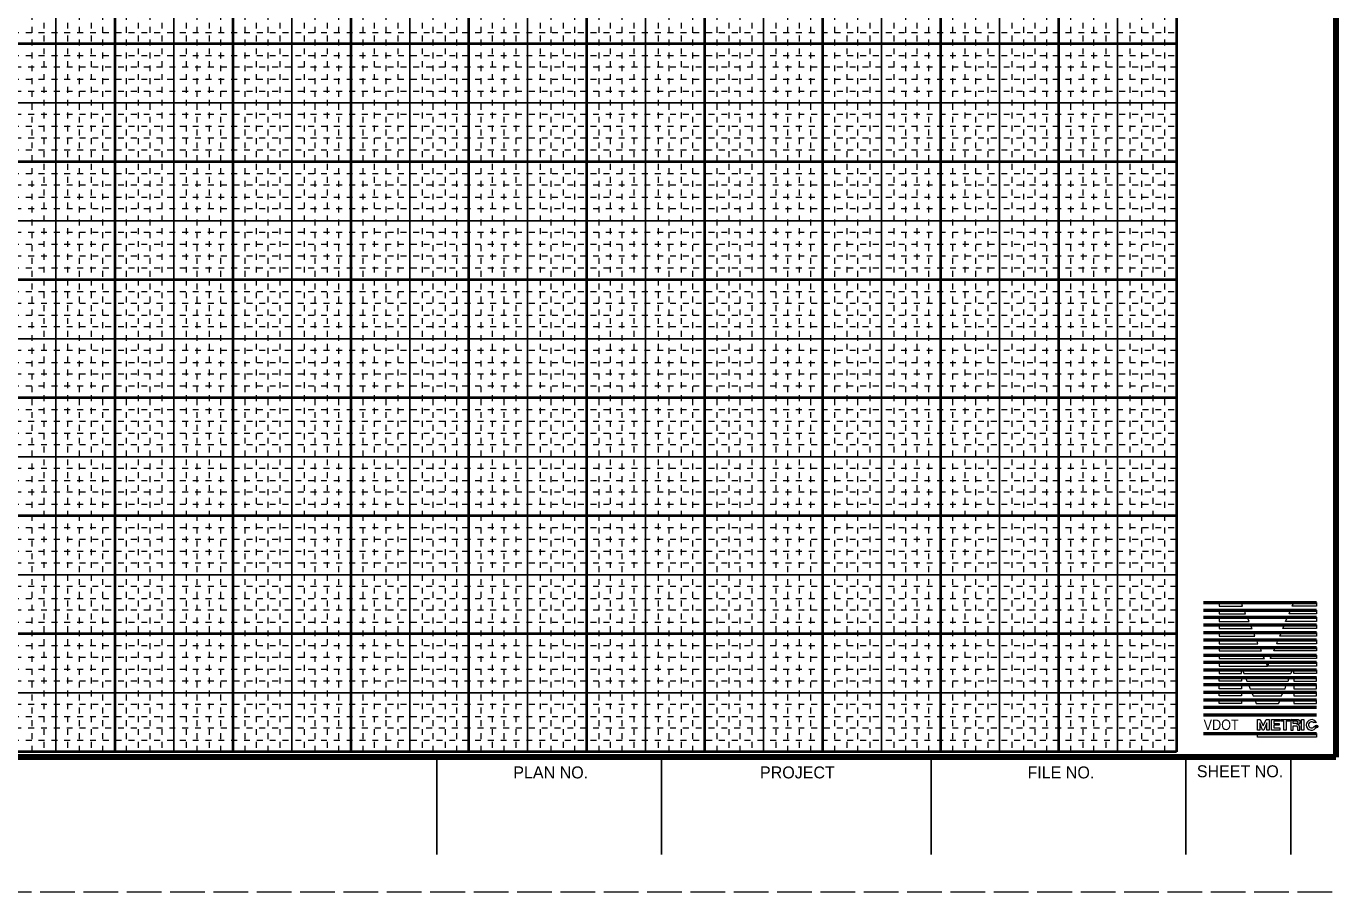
# Model space of a CAD drawing. Extents: x 224742 to 224831, y 224746 to 227695.
# Drawn here: x 224808.86 to 224831.11, y 225807.99 to 225822.66 of the extents above; entities that cross this region are included whole.
import ezdxf
from ezdxf.enums import TextEntityAlignment as Align

# ---------------------------------------------------------------- set-up
doc = ezdxf.new("R2010")
doc.units = 0
doc.header["$LTSCALE"] = 0.098
doc.header["$PDMODE"] = 32
doc.header["$PDSIZE"] = 0.049
doc.linetypes.add('DOTTED', pattern=[1.5, 0.3, -1.2])
doc.linetypes.add('LONG_DASHED', pattern=[7.5, 6, -1.5])
for name, color, linetype, lineweight in [('59', 7, 'DOTTED', 13), ('60', 7, 'Continuous', 40), ('61', 7, 'Continuous', 13), ('63', 7, 'LONG_DASHED', 13)]:
    doc.layers.add(name, color=color, linetype=linetype, lineweight=lineweight)

msp = doc.modelspace()

# ---------------------------------------------------------------- linework, layer by layer
at = {"layer": '59'}
for p, q in [((224808.9648, 225810.3649), (224808.9648, 225860.3649)), ((224809.1648, 225860.3649), (224809.1648, 225810.3649)), ((224809.5648, 225860.3649), (224809.5648, 225810.3649)), ((224809.7648, 225810.3649), (224809.7648, 225860.3649)), ((224809.9648, 225860.3649), (224809.9648, 225810.3649)), ((224810.1648, 225810.3649), (224810.1648, 225860.3649)), ((224810.5648, 225810.3649), (224810.5648, 225860.3649)), ((224810.7648, 225860.3649), (224810.7648, 225810.3649)), ((224810.9648, 225810.3649), (224810.9648, 225860.3649)), ((224811.1648, 225860.3649), (224811.1648, 225810.3649)), ((224811.5748, 225860.3649), (224811.5748, 225810.3649)), ((224811.7648, 225810.3649), (224811.7648, 225860.3649)), ((224811.9648, 225860.3649), (224811.9648, 225810.3649)), ((224812.1648, 225810.3649), (224812.1648, 225860.3649)), ((224812.5748, 225810.3649), (224812.5748, 225860.3649)), ((224812.7648, 225860.3649), (224812.7648, 225810.3649)), ((224812.9648, 225810.3649), (224812.9648, 225860.3649)), ((224813.1648, 225860.3649), (224813.1648, 225810.3649)), ((224813.5748, 225860.3649), (224813.5748, 225810.3649)), ((224813.7648, 225810.3649), (224813.7648, 225860.3649)), ((224813.9648, 225860.3649), (224813.9648, 225810.3649)), ((224814.1648, 225810.3649), (224814.1648, 225860.3649)), ((224814.5748, 225810.3649), (224814.5748, 225860.3649)), ((224814.7648, 225860.3649), (224814.7648, 225810.3649)), ((224814.9648, 225810.3649), (224814.9648, 225860.3649)), ((224815.1648, 225860.3649), (224815.1648, 225810.3649)), ((224815.5748, 225860.3649), (224815.5748, 225810.3649)), ((224815.7648, 225810.3649), (224815.7648, 225860.3649)), ((224815.9648, 225860.3649), (224815.9648, 225810.3649)), ((224816.1648, 225810.3649), (224816.1648, 225860.3649)), ((224816.5748, 225810.3649), (224816.5748, 225860.3649)), ((224816.7648, 225860.3649), (224816.7648, 225810.3649)), ((224816.9648, 225810.3649), (224816.9648, 225860.3649)), ((224817.1648, 225860.3649), (224817.1648, 225810.3649)), ((224817.5748, 225860.3649), (224817.5748, 225810.3649)), ((224817.7648, 225810.3649), (224817.7648, 225860.3649)), ((224817.9648, 225860.3649), (224817.9648, 225810.3649)), ((224818.1648, 225810.3649), (224818.1648, 225860.3649)), ((224818.5748, 225810.3649), (224818.5748, 225860.3649)), ((224818.7648, 225860.3649), (224818.7648, 225810.3649)), ((224818.9648, 225810.3649), (224818.9648, 225860.3649)), ((224819.1648, 225860.3649), (224819.1648, 225810.3649)), ((224819.5748, 225860.3649), (224819.5748, 225810.3649)), ((224819.7648, 225810.3649), (224819.7648, 225860.3649)), ((224819.9648, 225860.3649), (224819.9648, 225810.3649)), ((224820.1648, 225810.3649), (224820.1648, 225860.3649)), ((224820.5748, 225810.3649), (224820.5748, 225860.3649)), ((224820.7748, 225860.3649), (224820.7748, 225810.3649)), ((224820.9648, 225810.3649), (224820.9648, 225860.3649)), ((224821.1648, 225860.3649), (224821.1648, 225810.3649)), ((224821.5748, 225860.3649), (224821.5748, 225810.3649)), ((224821.7748, 225810.3649), (224821.7748, 225860.3649)), ((224821.9648, 225860.3649), (224821.9648, 225810.3649)), ((224822.1648, 225810.3649), (224822.1648, 225860.3649)), ((224822.5748, 225810.3649), (224822.5748, 225860.3649)), ((224822.7748, 225860.3649), (224822.7748, 225810.3649)), ((224822.9648, 225810.3649), (224822.9648, 225860.3649)), ((224823.1648, 225860.3649), (224823.1648, 225810.3649)), ((224823.5748, 225860.3649), (224823.5748, 225810.3649)), ((224823.7748, 225810.3649), (224823.7748, 225860.3649)), ((224823.9648, 225860.3649), (224823.9648, 225810.3649)), ((224824.1648, 225810.3649), (224824.1648, 225860.3649)), ((224824.5748, 225810.3649), (224824.5748, 225860.3649)), ((224824.7748, 225860.3649), (224824.7748, 225810.3649)), ((224824.9648, 225810.3649), (224824.9648, 225860.3649)), ((224825.1648, 225860.3649), (224825.1648, 225810.3649)), ((224825.5748, 225860.3649), (224825.5748, 225810.3649)), ((224825.7748, 225810.3649), (224825.7748, 225860.3649)), ((224825.9648, 225860.3649), (224825.9648, 225810.3649)), ((224826.1648, 225810.3649), (224826.1648, 225860.3649)), ((224826.5748, 225810.3649), (224826.5748, 225860.3649)), ((224826.7748, 225860.3649), (224826.7748, 225810.3649)), ((224826.9648, 225810.3649), (224826.9648, 225860.3649)), ((224827.1648, 225860.3649), (224827.1648, 225810.3649)), ((224827.5748, 225860.3649), (224827.5748, 225810.3649)), ((224827.7748, 225810.3649), (224827.7748, 225860.3649)), ((224827.9648, 225860.3649), (224827.9648, 225810.3649)), ((224828.1648, 225810.3649), (224828.1648, 225860.3649)), ((224748.3648, 225822.5549), (224828.3648, 225822.5549)), ((224748.3648, 225822.1649), (224828.3648, 225822.1649)), ((224828.3648, 225821.9649), (224748.3648, 225821.9649)), ((224748.3648, 225821.7649), (224828.3648, 225821.7649)), ((224828.3648, 225821.5549), (224748.3648, 225821.5549)), ((224828.3648, 225821.1649), (224748.3648, 225821.1649)), ((224748.3648, 225820.9649), (224828.3648, 225820.9649)), ((224828.3648, 225820.7649), (224748.3648, 225820.7649)), ((224748.3648, 225820.5649), (224828.3648, 225820.5649)), ((224748.3648, 225820.1649), (224828.3648, 225820.1649)), ((224828.3648, 225819.9649), (224748.3648, 225819.9649)), ((224748.3648, 225819.7649), (224828.3648, 225819.7649)), ((224828.3648, 225819.5649), (224748.3648, 225819.5649)), ((224828.3648, 225819.1649), (224748.3648, 225819.1649)), ((224748.3648, 225818.9649), (224828.3648, 225818.9649)), ((224828.3648, 225818.7649), (224748.3648, 225818.7649)), ((224748.3648, 225818.5649), (224828.3648, 225818.5649)), ((224748.3648, 225818.1649), (224828.3648, 225818.1649)), ((224828.3648, 225817.9649), (224748.3648, 225817.9649)), ((224748.3648, 225817.7649), (224828.3648, 225817.7649)), ((224828.3648, 225817.5649), (224748.3648, 225817.5649)), ((224828.3648, 225817.1649), (224748.3648, 225817.1649)), ((224748.3648, 225816.9649), (224828.3648, 225816.9649)), ((224828.3648, 225816.7649), (224748.3648, 225816.7649)), ((224748.3648, 225816.5649), (224828.3648, 225816.5649)), ((224748.3648, 225816.1649), (224828.3648, 225816.1649)), ((224828.3648, 225815.9649), (224748.3648, 225815.9649)), ((224748.3648, 225815.7649), (224828.3648, 225815.7649)), ((224828.3648, 225815.5649), (224748.3648, 225815.5649)), ((224828.3648, 225815.1649), (224748.3648, 225815.1649)), ((224748.3648, 225814.9649), (224828.3648, 225814.9649)), ((224828.3648, 225814.7649), (224748.3648, 225814.7649)), ((224748.3648, 225814.5649), (224828.3648, 225814.5649)), ((224748.3648, 225814.1649), (224828.3648, 225814.1649)), ((224828.3648, 225813.9649), (224748.3648, 225813.9649)), ((224748.3648, 225813.7649), (224828.3648, 225813.7649)), ((224828.3648, 225813.5649), (224748.3648, 225813.5649)), ((224828.3648, 225813.1649), (224748.3648, 225813.1649)), ((224748.3648, 225812.9649), (224828.3648, 225812.9649)), ((224828.3648, 225812.7649), (224748.3648, 225812.7649)), ((224748.3648, 225812.5649), (224828.3648, 225812.5649)), ((224748.3648, 225812.1649), (224828.3648, 225812.1649)), ((224828.3648, 225811.9649), (224748.3648, 225811.9649)), ((224748.3648, 225811.7649), (224828.3648, 225811.7649)), ((224828.3648, 225811.5649), (224748.3648, 225811.5649)), ((224828.3648, 225811.1649), (224748.3648, 225811.1649)), ((224748.3648, 225810.9649), (224828.3648, 225810.9649)), ((224828.3648, 225810.7649), (224748.3648, 225810.7649)), ((224748.3648, 225810.5649), (224828.3648, 225810.5649))]:
    msp.add_line(p, q, dxfattribs=at)
at = {"layer": '59', "linetype": 'Continuous', "lineweight": 25}
for p, q in [((224809.3648, 225810.3649), (224809.3648, 225860.3649)), ((224811.3648, 225810.3649), (224811.3648, 225860.3649)), ((224813.3648, 225810.3649), (224813.3648, 225860.3649)), ((224815.3648, 225810.3649), (224815.3648, 225860.3649)), ((224817.3648, 225810.3649), (224817.3648, 225860.3649)), ((224819.3648, 225810.3649), (224819.3648, 225860.3649)), ((224821.3648, 225810.3649), (224821.3648, 225860.3649)), ((224823.3648, 225810.3649), (224823.3648, 225860.3649)), ((224825.3648, 225810.3649), (224825.3648, 225860.3649)), ((224827.3648, 225810.3649), (224827.3648, 225860.3649)), ((224748.3648, 225821.3649), (224828.3648, 225821.3649)), ((224748.3648, 225819.3649), (224828.3648, 225819.3649)), ((224748.3648, 225817.3649), (224828.3648, 225817.3649)), ((224748.3648, 225815.3649), (224828.3648, 225815.3649)), ((224748.3648, 225813.3649), (224828.3648, 225813.3649)), ((224748.3648, 225811.3649), (224828.3648, 225811.3649))]:
    msp.add_line(p, q, dxfattribs=at)
at = {"layer": '60'}
for p, q in [((224810.3648, 225860.3649), (224810.3648, 225810.3649)), ((224812.3648, 225860.3649), (224812.3648, 225810.3649)), ((224814.3648, 225860.3649), (224814.3648, 225810.3649)), ((224816.3648, 225860.3649), (224816.3648, 225810.3649)), ((224818.3648, 225860.3649), (224818.3648, 225810.3649)), ((224820.3648, 225860.3649), (224820.3648, 225810.3649)), ((224822.3648, 225860.3649), (224822.3648, 225810.3649)), ((224824.3648, 225860.3649), (224824.3648, 225810.3649)), ((224826.3648, 225860.3649), (224826.3648, 225810.3649)), ((224828.3648, 225860.3649), (224828.3648, 225810.3649)), ((224828.3648, 225822.3649), (224748.3648, 225822.3649)), ((224828.3648, 225820.3649), (224748.3648, 225820.3649)), ((224828.3648, 225818.3649), (224748.3648, 225818.3649)), ((224828.3648, 225816.3649), (224748.3648, 225816.3649)), ((224828.3648, 225814.3649), (224748.3648, 225814.3649)), ((224828.3648, 225812.3649), (224748.3648, 225812.3649)), ((224828.3648, 225810.3649), (224748.3648, 225810.3649))]:
    msp.add_line(p, q, dxfattribs=at)
at = {"layer": '61', "lineweight": 158}
for p, q in [((224831.0648, 225864.1249), (224831.0648, 225810.2749)), ((224831.0648, 225810.2749), (224745.7148, 225810.2749))]:
    msp.add_line(p, q, dxfattribs=at)
at = {"layer": '61', "lineweight": 53}
for p, q in [((224828.8248, 225812.8949), (224830.7348, 225812.8949)), ((224828.8248, 225812.7649), (224830.7348, 225812.7649)), ((224828.8248, 225812.6449), (224830.7348, 225812.6449)), ((224828.8248, 225812.5149), (224830.7348, 225812.5149)), ((224828.8248, 225812.3849), (224830.7348, 225812.3849)), ((224828.8248, 225812.2649), (224830.7348, 225812.2649)), ((224828.8248, 225812.1349), (224830.7348, 225812.1349)), ((224828.8248, 225812.0049), (224830.7348, 225812.0049)), ((224828.8248, 225811.8849), (224830.7348, 225811.8849)), ((224828.8248, 225811.7549), (224830.7348, 225811.7549)), ((224828.8248, 225811.6249), (224830.7348, 225811.6249)), ((224828.8248, 225811.5049), (224830.7348, 225811.5049)), ((224828.8248, 225811.3749), (224830.7348, 225811.3749)), ((224828.8248, 225811.2449), (224830.7348, 225811.2449)), ((224828.8248, 225811.1249), (224830.7348, 225811.1249)), ((224828.8248, 225810.9949), (224830.7348, 225810.9949)), ((224828.8248, 225810.6749), (224830.7348, 225810.6749))]:
    msp.add_line(p, q, dxfattribs=at)
at = {"layer": '61'}
for p, q in [((224829.0848, 225812.0749), (224829.8048, 225812.0749)), ((224829.0848, 225811.9449), (224829.8548, 225811.9449)), ((224830.7348, 225811.9449), (224829.9548, 225811.9449)), ((224830.7348, 225812.0749), (224830.0148, 225812.0749)), ((224829.8848, 225811.8849), (224829.9048, 225811.8149)), ((224829.9348, 225811.8849), (224829.9048, 225811.8149)), ((224830.7348, 225810.8649), (224830.6848, 225810.8649)), ((224830.6948, 225810.7949), (224830.7348, 225810.7949))]:
    msp.add_line(p, q, dxfattribs=at)
at = {"layer": '61', "lineweight": 25}
for p, q in [((224831.0648, 225810.2749), (224815.8248, 225810.2749)), ((224815.8248, 225810.2749), (224815.8248, 225808.6249)), ((224831.0648, 225810.2749), (224815.8248, 225810.2749)), ((224819.6348, 225810.2749), (224819.6348, 225808.6249)), ((224824.2048, 225808.6249), (224824.2048, 225810.2749)), ((224828.5248, 225808.6249), (224828.5248, 225810.2749)), ((224830.3048, 225808.6249), (224830.3048, 225810.2749))]:
    msp.add_line(p, q, dxfattribs=at)
at = {"layer": '61'}
for points in [[(224829.0848, 225812.8949), (224829.0848, 225812.8349), (224829.4848, 225812.8349), (224829.4648, 225812.8949)], [(224830.7348, 225812.8949), (224830.7348, 225812.8349), (224830.3248, 225812.8349), (224830.3548, 225812.8949)], [(224829.0848, 225812.7649), (224829.0848, 225812.7049), (224829.5348, 225812.7049), (224829.5148, 225812.7649)], [(224829.0848, 225812.6449), (224829.0848, 225812.5749), (224829.5948, 225812.5749), (224829.5648, 225812.6449)], [(224830.7348, 225812.6449), (224830.7348, 225812.5749), (224830.2148, 225812.5749), (224830.2448, 225812.6449)], [(224830.7348, 225812.7649), (224830.7348, 225812.7049), (224830.2748, 225812.7049), (224830.2948, 225812.7649)], [(224829.0848, 225812.5149), (224829.0848, 225812.4549), (224829.6448, 225812.4549), (224829.6148, 225812.5149)], [(224829.0848, 225812.3849), (224829.0848, 225812.3249), (224829.6948, 225812.3249), (224829.6748, 225812.3849)], [(224830.7348, 225812.3849), (224830.7348, 225812.3249), (224830.1148, 225812.3249), (224830.1448, 225812.3849)], [(224830.7348, 225812.5149), (224830.7348, 225812.4549), (224830.1648, 225812.4549), (224830.1948, 225812.5149)], [(224829.0848, 225812.2649), (224829.0848, 225812.1949), (224829.7448, 225812.1949), (224829.7248, 225812.2649)], [(224830.7348, 225812.2649), (224830.7348, 225812.1949), (224830.0648, 225812.1949), (224830.0848, 225812.2649)], [(224829.0848, 225812.1349), (224829.0848, 225812.0749), (224829.8048, 225812.0749), (224829.7748, 225812.1349)], [(224829.0848, 225812.0049), (224829.0848, 225811.9449), (224829.8548, 225811.9449), (224829.8248, 225812.0049)], [(224830.7348, 225812.0049), (224830.7348, 225811.9449), (224829.9548, 225811.9449), (224829.9848, 225812.0049)], [(224830.7348, 225812.1349), (224830.7348, 225812.0749), (224830.0148, 225812.0749), (224830.0348, 225812.1349)], [(224829.0848, 225811.8849), (224829.0848, 225811.8149), (224829.9048, 225811.8149), (224829.8848, 225811.8849)], [(224829.0848, 225811.7549), (224829.0848, 225811.6949), (224829.4648, 225811.6949), (224829.4648, 225811.7549)], [(224829.4848, 225811.7549), (224829.5048, 225811.6949), (224830.3048, 225811.6949), (224830.3348, 225811.7549)], [(224830.7348, 225811.8849), (224830.7348, 225811.8149), (224829.9048, 225811.8149), (224829.9348, 225811.8849)], [(224830.7348, 225811.7549), (224830.7348, 225811.6949), (224830.3548, 225811.6949), (224830.3548, 225811.7549)], [(224829.0848, 225811.6249), (224829.4648, 225811.6249), (224829.4648, 225811.5649), (224829.0848, 225811.5649)], [(224829.0848, 225811.5049), (224829.4648, 225811.5049), (224829.4648, 225811.4349), (224829.0848, 225811.4349)], [(224829.5348, 225811.6249), (224829.5548, 225811.5649), (224830.2548, 225811.5649), (224830.2748, 225811.6249)], [(224829.5848, 225811.5049), (224829.6148, 225811.4349), (224830.2048, 225811.4349), (224830.2248, 225811.5049)], [(224830.7348, 225811.6249), (224830.3548, 225811.6249), (224830.3548, 225811.5649), (224830.7348, 225811.5649)], [(224830.7348, 225811.5049), (224830.3548, 225811.5049), (224830.3548, 225811.4349), (224830.7348, 225811.4349)], [(224829.0848, 225811.3749), (224829.4648, 225811.3749), (224829.4648, 225811.3149), (224829.0848, 225811.3149)], [(224829.6348, 225811.3749), (224829.6648, 225811.3149), (224830.1448, 225811.3149), (224830.1748, 225811.3749)], [(224830.7348, 225811.3749), (224830.3548, 225811.3749), (224830.3548, 225811.3149), (224830.7348, 225811.3149)], [(224829.0848, 225811.2449), (224829.4648, 225811.2449), (224829.4648, 225811.1849), (224829.0848, 225811.1849)], [(224829.6948, 225811.2449), (224829.7148, 225811.1849), (224830.0948, 225811.1849), (224830.1248, 225811.2449)], [(224830.7348, 225811.2449), (224830.3548, 225811.2449), (224830.3548, 225811.1849), (224830.7348, 225811.1849)], [(224829.7348, 225810.7349), (224829.7348, 225810.9149), (224829.7848, 225810.9149), (224829.8348, 225810.8049), (224829.8848, 225810.9149), (224829.9348, 225810.9149), (224829.9348, 225810.7349), (224829.8948, 225810.7349), (224829.8948, 225810.8549), (224829.8448, 225810.7349), (224829.8248, 225810.7349), (224829.7748, 225810.8549), (224829.7748, 225810.7349)], [(224829.9748, 225810.7349), (224829.9748, 225810.9149), (224830.1148, 225810.9149), (224830.1148, 225810.8849), (224830.0148, 225810.8849), (224830.0148, 225810.8449), (224830.1048, 225810.8449), (224830.1048, 225810.8149), (224830.0148, 225810.8149), (224830.0148, 225810.7749), (224830.1148, 225810.7749), (224830.1148, 225810.7349)], [(224830.1348, 225810.8849), (224830.1348, 225810.9149), (224830.2848, 225810.9149), (224830.2848, 225810.8849), (224830.2248, 225810.8849), (224830.2248, 225810.7349), (224830.1848, 225810.7349), (224830.1848, 225810.8849)], [(224830.3048, 225810.9149), (224830.3048, 225810.7349), (224830.3448, 225810.7349), (224830.3448, 225810.8049), (224830.3948, 225810.8049), (224830.3948, 225810.8049), (224830.4048, 225810.8049), (224830.4048, 225810.8049), (224830.4048, 225810.8049), (224830.4048, 225810.8049), (224830.4048, 225810.7949), (224830.4148, 225810.7949), (224830.4148, 225810.7849), (224830.4148, 225810.7749), (224830.4148, 225810.7549), (224830.4148, 225810.7549), (224830.4148, 225810.7449), (224830.4148, 225810.7349), (224830.4148, 225810.7349), (224830.4548, 225810.7349), (224830.4548, 225810.7449), (224830.4548, 225810.7449), (224830.4548, 225810.7449), (224830.4548, 225810.7549), (224830.4548, 225810.7849), (224830.4548, 225810.7949), (224830.4448, 225810.8049), (224830.4448, 225810.8149), (224830.4448, 225810.8149), (224830.4448, 225810.8149), (224830.4448, 225810.8149), (224830.4348, 225810.8149), (224830.4348, 225810.8249), (224830.4348, 225810.8249), (224830.4248, 225810.8249), (224830.4248, 225810.8249), (224830.4248, 225810.8249), (224830.3948, 225810.8449), (224830.3448, 225810.8449), (224830.3448, 225810.8849)], [(224830.3048, 225810.9149), (224830.3748, 225810.9149), (224830.3948, 225810.9149), (224830.3948, 225810.9149), (224830.4048, 225810.9149), (224830.4148, 225810.9149), (224830.4148, 225810.9149), (224830.4248, 225810.9149), (224830.4248, 225810.9149), (224830.4248, 225810.9149), (224830.4348, 225810.9149), (224830.4348, 225810.9049), (224830.4448, 225810.9049), (224830.4448, 225810.9049), (224830.4448, 225810.9049), (224830.4548, 225810.8949), (224830.4548, 225810.8949), (224830.4548, 225810.8949), (224830.4548, 225810.8849), (224830.4548, 225810.8849), (224830.4548, 225810.8749), (224830.4548, 225810.8649), (224830.4548, 225810.8649), (224830.4548, 225810.8549), (224830.4548, 225810.8549), (224830.4548, 225810.8549), (224830.4548, 225810.8449), (224830.4548, 225810.8449), (224830.4448, 225810.8449), (224830.4448, 225810.8449), (224830.4448, 225810.8349), (224830.4448, 225810.8349), (224830.4348, 225810.8349), (224830.4348, 225810.8349), (224830.4248, 225810.8249), (224830.4248, 225810.8249), (224830.3948, 225810.8449), (224830.3948, 225810.8449), (224830.4048, 225810.8449), (224830.4048, 225810.8449), (224830.4148, 225810.8449), (224830.4148, 225810.8549), (224830.4148, 225810.8549), (224830.4148, 225810.8549), (224830.4248, 225810.8649), (224830.4248, 225810.8649), (224830.4248, 225810.8649), (224830.4248, 225810.8749), (224830.4148, 225810.8749), (224830.4148, 225810.8749), (224830.4148, 225810.8749), (224830.4148, 225810.8849), (224830.4048, 225810.8849), (224830.4048, 225810.8849), (224830.3948, 225810.8849), (224830.3448, 225810.8849)], [(224830.4848, 225810.7349), (224830.4848, 225810.9149), (224830.5248, 225810.9149), (224830.5248, 225810.7349)], [(224829.7348, 225810.6749), (224830.7348, 225810.6749), (224830.7348, 225810.6149), (224829.7348, 225810.6149)]]:
    msp.add_lwpolyline(points, close=True, dxfattribs=at)
for radius, start, end in [(0.0894, 24.50501, 339.37361), (0.0518, 45.69947, 322.56629)]:
    msp.add_arc((224830.6538, 225810.8221), radius, start, end, dxfattribs=at)
msp.add_point((224830.7348, 225810.7949), dxfattribs=at)
at = {"layer": '63'}
msp.add_lwpolyline([(224831.1148, 225866.3949), (224742.2148, 225866.3949), (224742.2148, 225807.9949), (224831.1148, 225807.9949)], dxfattribs=at)

# ---------------------------------------------------------------- texts
at = {"layer": '61', "width": 0.9}
msp.add_text('VDOT', height=0.1778, dxfattribs=at).set_placement((224828.8248, 225810.7349))
at = {"layer": '61'}
for s, p in [('SHEET NO.', (224829.4415, 225809.9341)), ('PLAN NO.', (224817.7557, 225809.9149)), ('PROJECT', (224821.9377, 225809.9149)), ('FILE NO.', (224826.405, 225809.9149))]:
    msp.add_text(s, height=0.2032, dxfattribs=at).set_placement(p, align=Align.CENTER)

doc.saveas('drawing.dxf')
